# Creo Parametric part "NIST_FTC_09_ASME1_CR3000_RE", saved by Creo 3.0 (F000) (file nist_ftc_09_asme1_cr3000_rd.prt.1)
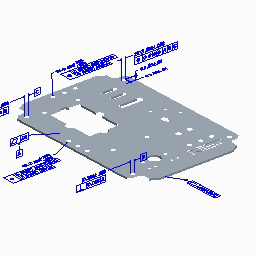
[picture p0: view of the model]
Units: Inch lbm Second (Pro/E Default); INCH, POUND, SECS

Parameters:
  PART_NUMBER = "NIST PMI FTC 09 ASME1"
  REVISION = "D"
  DESCRIPTION = "NIST PMI test model downloaded from http://go.usa.gov/mGVm"
  COPY_GEOM_ORIGIN = "NIST_FTC_09_ASME1_CR3000_RE"
  COPY_GEOM_ORIGIN_TYPE = "Part"

Created from: NIST_FTC_09_ASME1_CR3000_RD.PRT

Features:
  1. datum plane "RIGHT"
  2. datum plane "TOP"
  3. datum plane "FRONT"
  4. coordinate system
  5. curve
  6. protrusion
  7. pattern
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
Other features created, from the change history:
  extrusion "Extrude 6"
  annotation "Annotation 38" (2 times)
  annotation "Annotation 39"
  annotation "Annotation 40"
  annotation "Annotation 41"
  annotation "Annotation 42"

Other named items: ABC, AGH, ABD, AF, A, H, B, C, F, G, D, E, AE_NOTE0, AE_GTOL0, AE_SET_DATUM_TAG_A, AE_DRIVEN_DIM0, AE_GTOL1, AE_SET_DATUM_TAG_B, AE_DRIVEN_DIM1, AE_GTOL2, AE_SET_DATUM_TAG_C, AE_DRIVEN_DIM2, AE_DRIVEN_DIM4, AE_GTOL4, AE_DRIVEN_DIM6, AE_GTOL6, AE_DRIVEN_DIM7, AE_GTOL7, AE_NOTE2, AE_NOTE3, AE_DRIVEN_DIM9, AE_GTOL9, AE_SET_DATUM_TAG_F, AE_GTOL10, AE_DRIVEN_DIM10, AE_GTOL11, AE_DRIVEN_DIM11, AE_GTOL12, AE_SET_DATUM_TAG_G, AE_SET_DATUM_TAG_H, AE_GTOL13, AE_GTOL14, AE_DRIVEN_DIM12, AE_DRIVEN_DIM13, AE_GTOL15, AE_DRIVEN_DIM14, AE_GTOL16, AE_DRIVEN_DIM15, AE_GTOL17, AE_SET_DATUM_TAG_D, AE_DRIVEN_DIM16, AE_GTOL18, AE_SET_DATUM_TAG_E, AE_GTOL19, AE_DRIVEN_DIM17, AE_GTOL20, AE_DRIVEN_DIM18, AE_GTOL21, AE_DRIVEN_DIM19, AE_DRIVEN_DIM20, AE_GTOL22, AE_GTOL23, AE_DRIVEN_DIM21, AE_GTOL24, AE_DRIVEN_DIM22, AE_GTOL25, AE_DRIVEN_DIM23, AE_GTOL27, AE_GTOL28, AE_GTOL29, AE_DRIVEN_DIM24, AE_GTOL30, AE_DRIVEN_DIM25, AE_DRIVEN_DIM26, AE_DRIVEN_DIM27, AE_GTOL31, AE_DRIVEN_DIM28, AE_DRIVEN_DIM29, AE_GTOL32, MBD_A, MBD_B, MBD_C, MBD_D, LAYER_STATE001, LAYER_STATE002, LAYER_STATE003, ANNOT_LAYER_STATE0001, ANNOT_LAYER_STATE0002, ANNOT_LAYER_STATE0003, ANNOT_LAYER_STATE0004, LAYER_STATE004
